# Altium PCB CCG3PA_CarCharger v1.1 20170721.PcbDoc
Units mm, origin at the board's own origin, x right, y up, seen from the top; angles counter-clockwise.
Board outline 152.4 x 101.6 mm, 4 copper layers (Top Layer, MidLayer1, MidLayer2, Bottom Layer); 67 components, 48 nets, 247 pads, 127 vias.
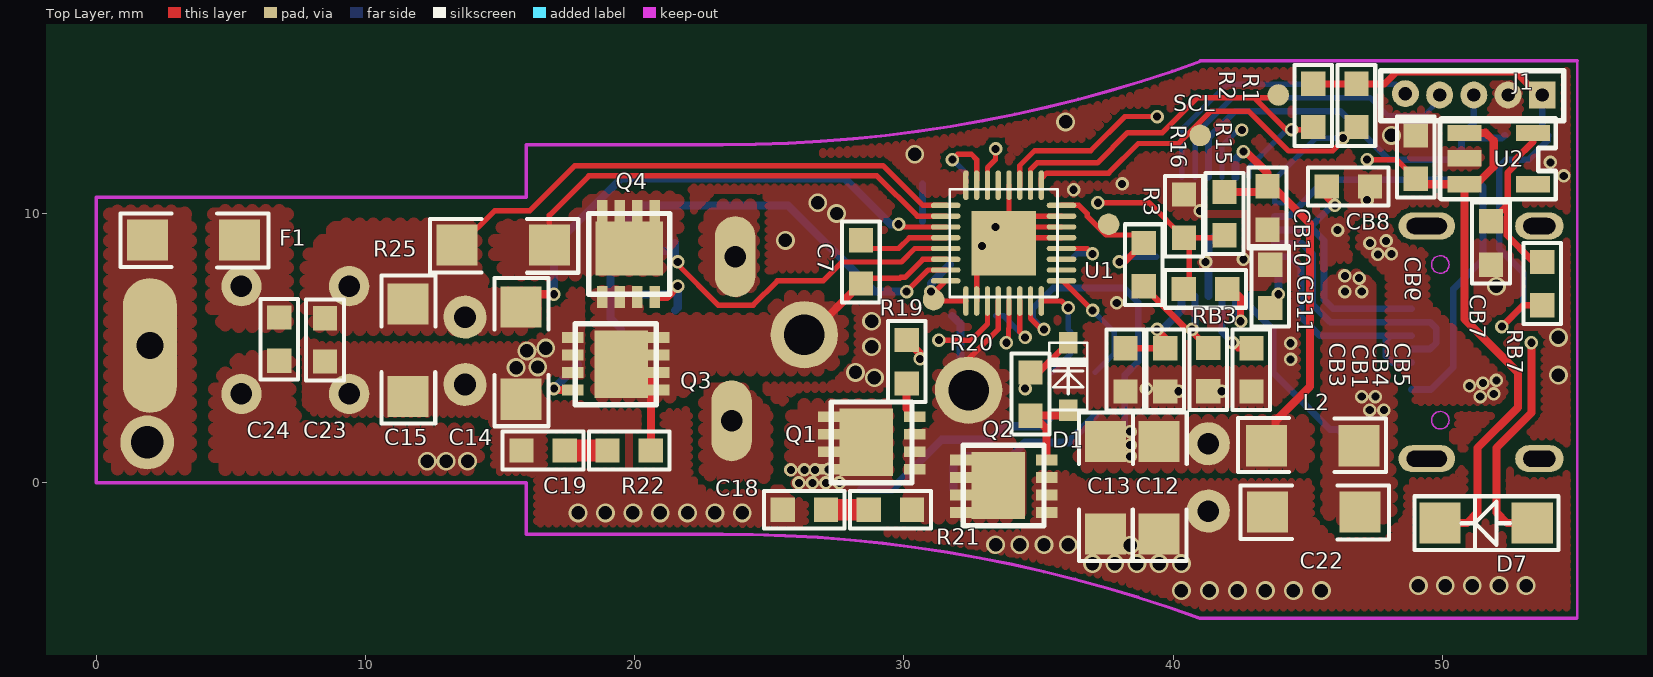
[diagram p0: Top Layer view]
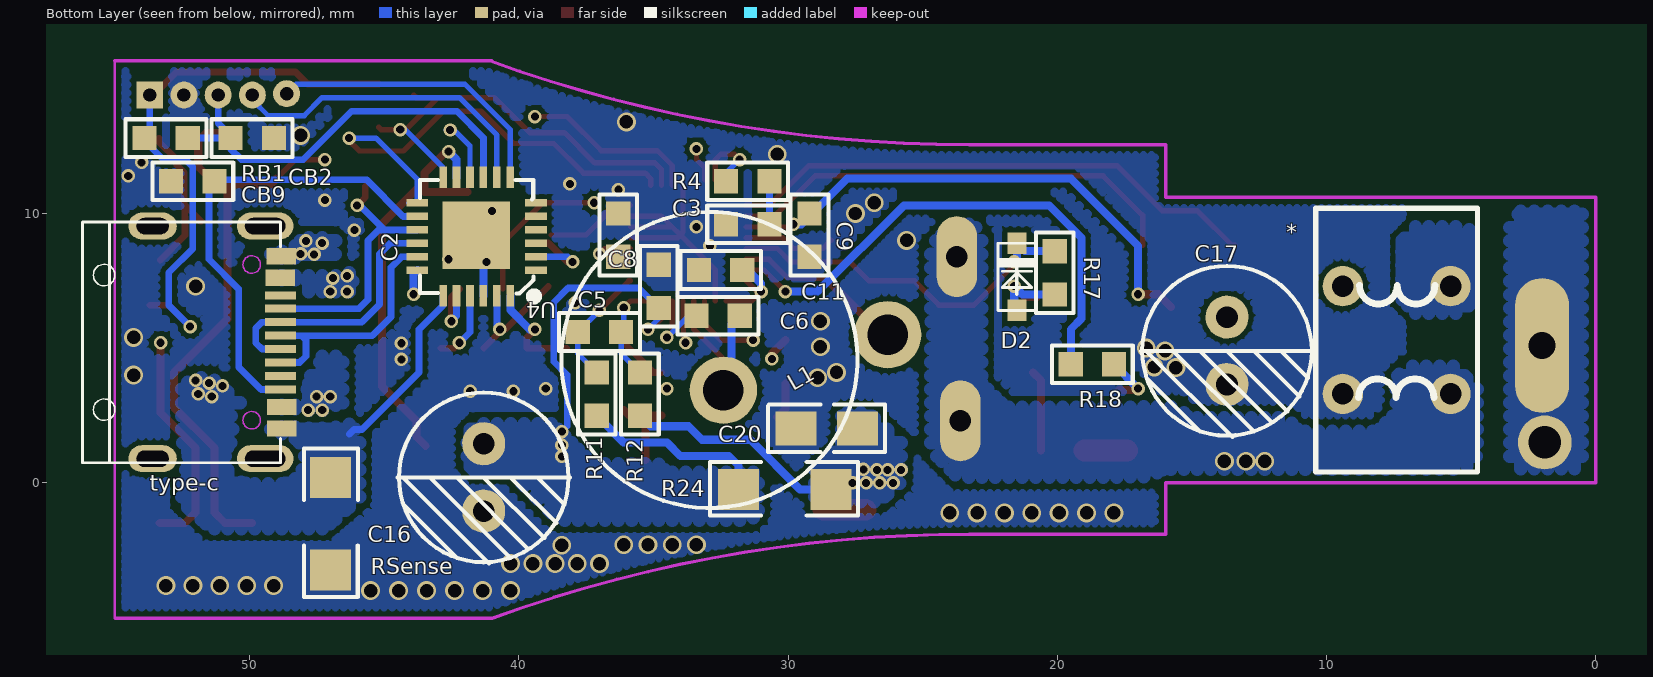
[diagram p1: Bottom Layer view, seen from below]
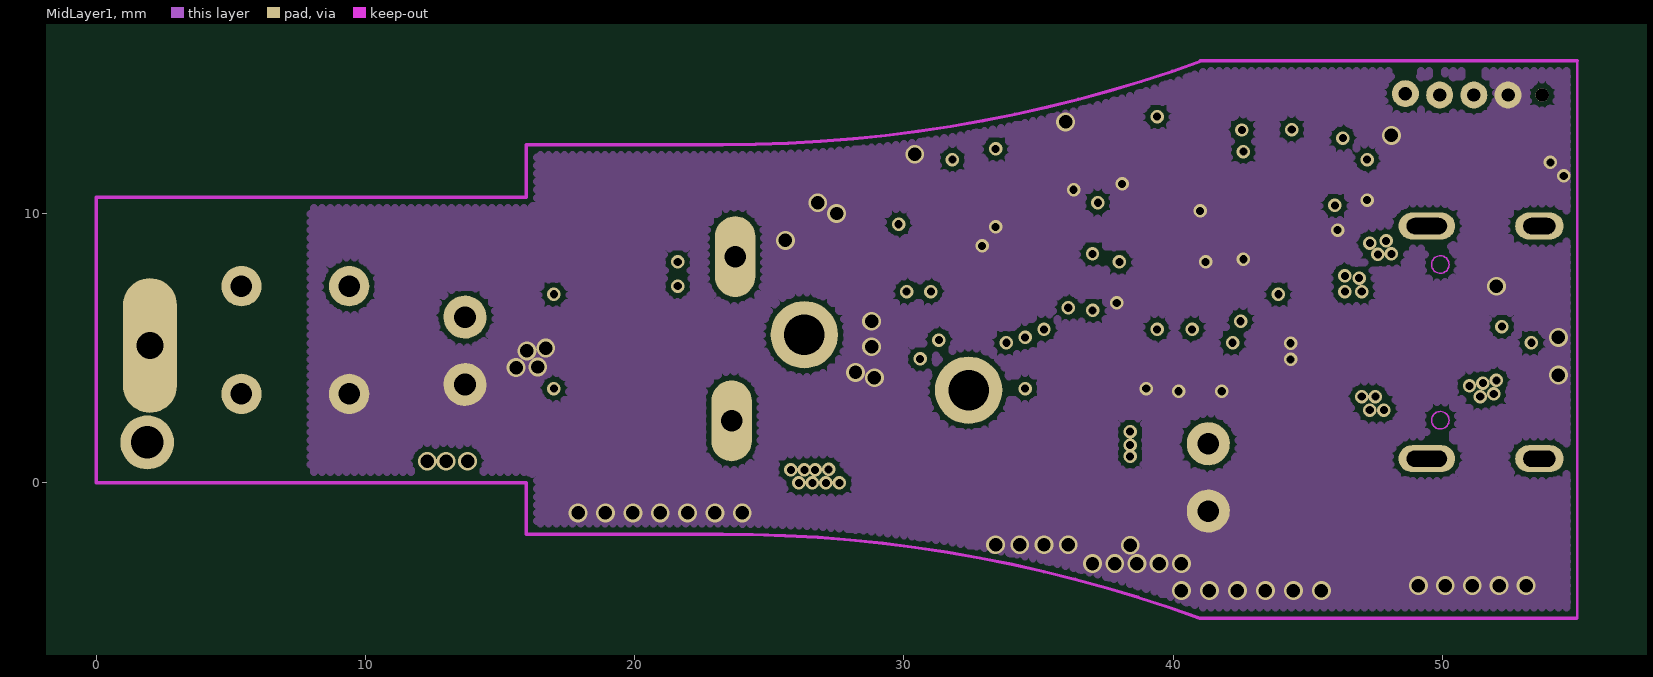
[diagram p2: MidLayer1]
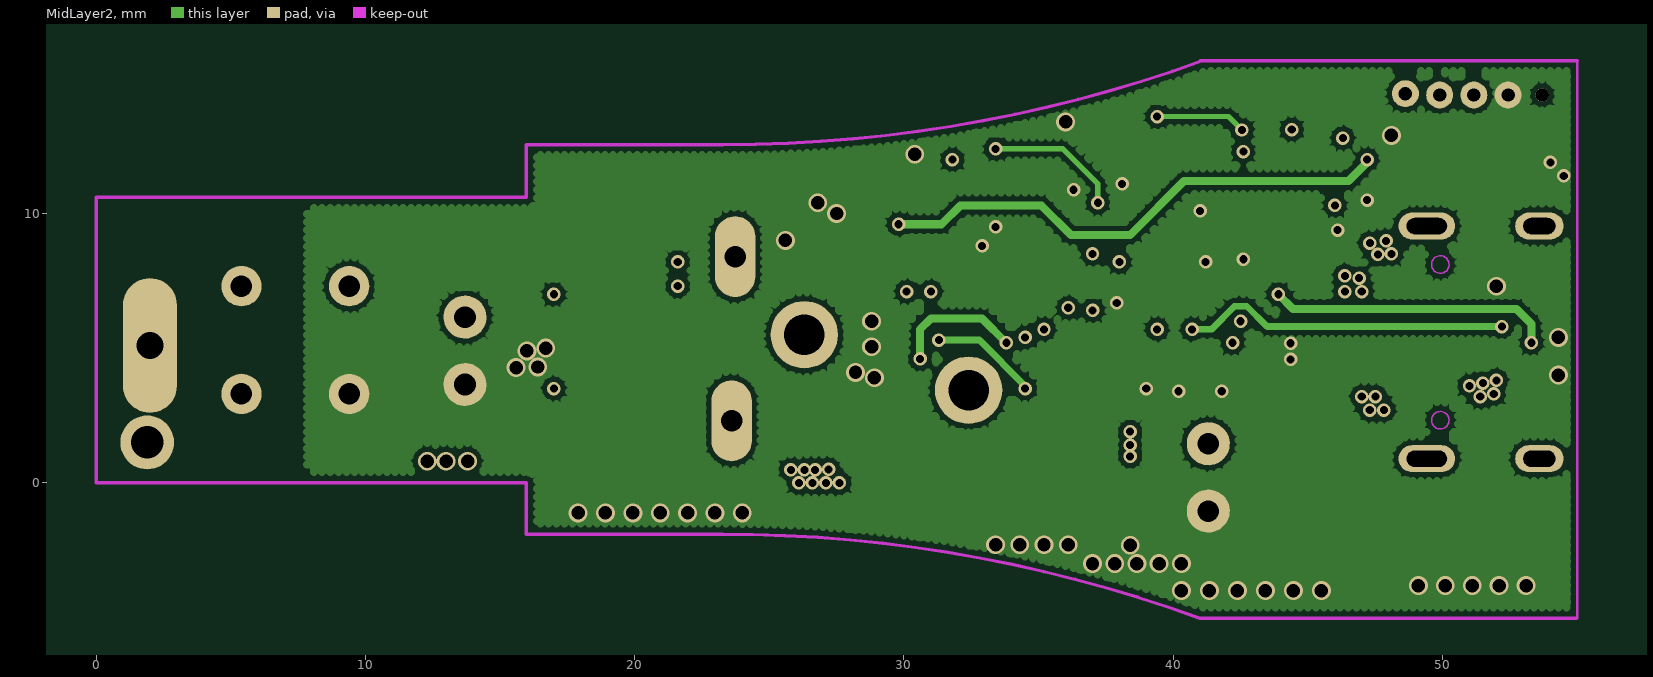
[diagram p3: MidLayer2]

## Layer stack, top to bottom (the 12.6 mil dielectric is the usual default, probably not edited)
Top Layer: signal copper 0.0356
Dielectric: core 0.32, FR-4, Dk 4.8
MidLayer1: signal copper 0.0356
Dielectric: prepreg 0.32, FR-4, Dk 4.8
MidLayer2: signal copper 0.0356
Dielectric: core 0.32, FR-4, Dk 4.8
Bottom Layer: signal copper 0.0356

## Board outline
-65.803,-29.119 86.597,-29.119 86.597,72.481 -65.803,72.481

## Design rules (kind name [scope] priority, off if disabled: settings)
Clearance [All] p1: gap=0.18
ComponentClearance [All] p1: gap=0 collisioncheckmode=3 verticalgap=0 showdistances=FALSE
HoleToHoleClearance [All] p1: gap=0 allowstackedmicrovias=TRUE
MinimumSolderMaskSliver [All] p1: minsoldermaskwidth=0
PlaneConnect [All] p1: planeconnectstyle=Direct reliefexpansion=0.508 reliefentries=4 reliefconductorwidth=0.254 reliefairgap=0.254
PolygonConnect [All] p1: connectstyle=Direct reliefconductorwidth=0.254 reliefentries=4 polygonreliefangle="90 Angle" airgapwidth=0.254
RoutingVias [All] p1: holewidth=0.711 width=1.27 viastyle="Through Hole" minholewidth=0.711 minwidth=1.27 maxholewidth=0.711 maxwidth=1.27
ShortCircuit [InNet('GND') And OnLayer('MidLayer1') vs InNet('SGND') And OnLayer('MidLayer1')] p1: allowed=TRUE
SilkToSilkClearance [All] p1: silktosilkclearance=0
SilkToSolderMaskClearance SilkscreenOverComponentPads [IsPad] p1: minsilkscreentomaskgap=0 clearancetoexposedcopper=TRUE
SolderMaskExpansion [All] p1: expansion=0.102
Width [All] p1: maxlimit=11 minlimit=0.2 preferedwidth=0.3
21 further rules are at their usual default settings.

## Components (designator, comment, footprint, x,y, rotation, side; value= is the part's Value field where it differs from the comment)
* "COMMON" Common1 9.4,3.3 r180 bottom locked
C2 "100nF" 0603 36.3,8.4 r90 bottom
C3 "10nF" 0603 30.7,9.6 r0 bottom
C5 "22nF" 0603 37.8,5.6 r180 bottom
C6 "0.1uF" 0603 31.8,6.2 r0 bottom
C7 "0.1uF" 0603 28.4,9 r270 top
C8 "1uF" 0603 34.8,6.5 r90 bottom
C9 "1uF" 0603 29.2,8.4 r90 bottom
C11 "1uF" 0603 33.3,7.9 r180 bottom
C12 "10uF/35V" 1206#1 40.2,2.3 r270 top
C13 "10uF/35V" 1206#1 38.2,2.3 r270 top
C14 "10uF/35V" 1206#1 16.5,7.3 r270 top
C15 "10uF/35V" 1206#1 12.3,7.4 r270 top
C16 "100uF" C4 41.3,1.4 r270 bottom
C17 "100uF" C4 13.7,6.1 r270 bottom
C18 "1nF" 0603 27.1,-1 r180 top
C19 "1nF" 0603 17.4,1.2 r180 top
C20 "100nF" 0805 26.4,1 r0 bottom
C22 "10uF/25V" 1206#1 47.7,-1.8 r180 top
C23 "0.1uF" 0603 8.5,6.1 r270 top
C24 "0.1uF" 0603 6.803,6.133 r270 top
CB1 "1uF" 0603 39.7,3.4 r90 top
CB2 "0.1u" 0603 49.1,12.8 r0 bottom
CB3 "0.1uF" 0603 38.222,4.992 r270 top
CB4 "1uF" 0603 41.3,5 r270 top
CB5 "0.1uF" 0603 42.9,3.4 r90 top
CB6 "1uF" 0603 49,11.3 r90 top
CB7 "1uF" 0603 51.8,9.7 r270 top
CB8 "390pF" 0603 47.3,11 r180 top
CB9 "390pF" 0603 52.9,11.2 r180 bottom
CB10 "1uF" 0603 43.5,11 r270 top
CB11 "1uF" 0603 43.6,6.5 r90 top
D1 "4148" sod323 36.1,5.2 r270 top
D2 "4148" sod323 21.5,8.9 r270 bottom
D7 "5.1V" D1206 49.9,-1.5 r0 top
F1 "FUSE" 1206#1 6.1,8.3 r180 top
J1 "PIN5" pin5 53.7,14.4 r180 top
L1 "6.8uH" L/DB_MPP 26.3,5.5 r330 bottom locked
L2 "Bead" 1206#1 42.7,2.1 r0 top
Q1 "PK616" PDFN-3*3 30.4,0.5 r180 top
Q2 "PK616" PDFN-3*3 35.3,-1.1 r180 top
Q3 "3482" PDFN-3*3 17.7,5.4 r0 top
Q4 "3482" PDFN-3*3 18.8,6.9 r90 top
R1 "10K" 0603 46.8,14.808 r270 top
R2 "10K" 0603 45.2,14.808 r270 top
R3 "10K" 0603 38.9,8.9 r270 top
R4 "20k" 0603 30.7,11.2 r0 bottom
R11 "2R2" 0603 37.1,2.5 r90 bottom
R12 "2R2" 0603 35.5,2.5 r90 bottom
R15 "100k" 0603 41.9,9.2 r90 top
R16 "24k" 0603 40.4,10.7 r270 top
R17 "20R0" 0603 20.1,7 r90 bottom
R18 "0R0" 0603 17.9,4.4 r0 bottom
R19 "0R0" 0603 30.1,3.7 r90 top
R20 "20R0" 0603 34.7,2.5 r90 top
R21 "2R2" 0603 28.7,-1 r0 top
R22 "2R2" 0603 19,1.2 r0 top
R24 "0R010" 1206#1 32.6,0.481 r180 bottom
R25 "0R005" 1206#1 17.6,8.1 r180 top
RB1 "4.7K" 0603 52.3,12.8 r0 bottom
RB3 "0R0" 0603 40.4,7.2 r0 top
RB7 "10R0/NC" 0603 53.7,6.6 r90 top
RSense "0R005" 1206#2 46.997,-1.519 r270 bottom
type-c "TYPE-C" type-c3 49.1,5.7 r0 bottom locked
U1 "SC8815" TQFN32-4*4L 35.7,7.5 r180 top
U2 "3.3V/NC" SOT-23-5 49.8,13.5 r270 top
U4 "CCG3PA" QFN-24 39.9,7.2 r0 bottom

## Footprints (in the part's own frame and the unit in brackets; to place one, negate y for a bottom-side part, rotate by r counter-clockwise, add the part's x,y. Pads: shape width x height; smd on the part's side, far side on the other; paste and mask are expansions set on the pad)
0603 [mm]
  rect 0.9x0.9 smd: 1(-0.008,0) 2(1.6,0)
  silkscreen extent -0.7,-0.7 2.3,0.7, body extent -0.05,-0.45 1.6,0.45, height 1
0805 [mil]
  rect 60x50 smd: 1(40,-40) 2(130,-40)
  silkscreen extent 0,-75 171,-6, body extent 41,-65 130,-16, height 39
1206#1 [mil]
  rect 60x60 smd: 1(30.24,-28.5) 2(165.24,-28.5)
  silkscreen extent -12,-67 205,12, body extent 30,-59 167,2, height 39
1206#2 [mil]
  rect 60x60 smd: 1(-67.5,0) 2(67.5,0)
  silkscreen extent -110,-38 107,40, body extent -68,-31 70,30, height 39
C4 [mm]
  round 1.6 hole 0.8: 1(-0.05,0) 2(2.45,0)
  silkscreen extent -1.95,-3.2 4.4,3.2, body extent -1.7,-3.1 4.28,2.89, height 8
Common1 [mm]
  round 1.5 hole 0.8: 1(0,0) 2(4,0) 3(0,4) 4(4,4)
  silkscreen extent -1,-2.9 5,6.9
D1206 [mil]
  rect 60x60 smd: 1(135,0) 2(0,0)
  silkscreen extent -37,-39 173,39
L/DB_MPP [mm]
  round 2.5 hole 1.5: 1(0,0) 2(6.312,-1.267)
  silkscreen extent 0.7,-8 11.7,3
PDFN-3*3 [mm]
  rect 0.8x0.4 smd: 1(0,-1.95) 2(3.2,-1.3) 2(3.2,-0.65) 2(3.2,0) 2(3.2,-1.95) 3(0,0) 3(0,-0.65) 3(0,-1.3)
  rect 2x2.5 smd: 2(1.8,-1)
  silkscreen extent 0.1,-2.5 3.1,0.5
pin5 [mm]
  rect 1x1 / inner round 0.5 / far side rect 1x1 hole 0.5: 1(0,0)
  round 1 hole 0.5: 2(1.27,0) 3(2.54,0) 4(3.81,0) 5(5.08,-0.05)
  silkscreen extent -0.8,-0.9 6,0.95
QFN-24 [mm]
  rect 2.5x2.5 smd: 0(1.672,-1.987)
  rect 0.8x0.28 smd: 1(-0.542,-0.691) 2(-0.542,-1.191) 3(-0.542,-1.691) 4(-0.542,-2.191) 5(-0.542,-2.691) 6(-0.542,-3.191) 13(3.862,-3.191) 14(3.862,-2.691) 15(3.862,-2.191) 16(3.862,-1.691) 17(3.862,-1.191) 18(3.862,-0.691)
  rect 0.28x0.8 smd: 7(0.41,-4.143) 8(0.91,-4.143) 9(1.41,-4.143) 10(1.91,-4.143) 11(2.41,-4.143) 12(2.91,-4.143) 19(2.91,0.26) 20(2.41,0.26) 21(1.91,0.26) 22(1.41,0.26) 23(0.91,0.26) 24(0.41,0.26)
  silkscreen extent -0.61,-4.04 3.76,0.43, body extent -0.46,-4.07 3.78,0.17, height 0.72
sod323 [mm]
  rect 0.8x0.7 smd: 1(2.5,0) 2(0,0)
  silkscreen extent 0,-0.7 2.5,0.7
SOT-23-5 [mil]
  rect 23.62x50 smd: 1(20,40) 2(57,40) 3(95,40) 4(95,140) 5(20,140)
  silkscreen extent -1,4 117,173
TQFN32-4*4L [mm]
  round 0.5 on Top Overlay: 0(0.05,0.55)
  rect 2.4x2.4 smd: 0(2,-1.4)
  oval 1.1x0.2 smd: 1(-0.15,0) 2(-0.15,-0.4) 3(-0.15,-0.8) 4(-0.15,-1.2) 5(-0.15,-1.6) 6(-0.15,-2) 7(-0.15,-2.4) 8(-0.15,-2.8) 17(4.15,-2.8) 18(4.15,-2.4) 19(4.15,-2) 20(4.15,-1.6) 21(4.15,-1.2) 22(4.15,-0.8) 23(4.15,-0.4) 24(4.15,0)
  oval 0.2x1.1 smd: 9(0.6,-3.55) 10(1,-3.55) 11(1.4,-3.55) 12(1.8,-3.55) 13(2.2,-3.55) 14(2.6,-3.55) 15(3,-3.55) 16(3.4,-3.55) 25(3.4,0.75) 26(3,0.75) 27(2.6,0.75) 28(2.2,0.75) 29(1.8,0.75) 30(1.4,0.75) 31(1,0.75) 32(0.6,0.75)
  silkscreen extent 0,-3.4 4,0.6
type-c3 [mm]
  rect 1.1x0.6 smd: A1B12(-0.275,-2.715) A4B9(-0.25,-1.915) B1A12(-0.3,3.685) B4A9(-0.3,2.885)
  rect 1.15x0.3 smd: A5(-0.25,-0.765) A6(-0.25,0.235) A7(-0.25,0.735) A8(-0.25,1.735) B5(-0.25,2.235) B6(-0.25,1.235) B7(-0.25,-0.265) B8(-0.25,-1.25)
  oval 2.1x1 hole 0.6 slot 1.5 at 0 deg: GND(0.315,-3.835) GND(0.315,4.805)
  oval 1.8x1 hole 0.6 slot 1.2 at 0 deg: GND(4.495,-3.835) GND(4.495,4.805)
  Keep-Out Layer circle w0.05: c0.815,-2.405 r0.325
  Keep-Out Layer circle w0.05: c0.815,3.375 r0.325
  silkscreen extent -0.26,-3.99 7.09,4.96

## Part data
C2 C3 C5 C6 C7 C8 C9 C11 C12 C13 C14 C15 C18 C19 C20 C22 C23 C24 CB1 CB2 CB3 CB4 CB5 CB6 CB7 CB8 CB9 CB10 CB11: library part CAP, "cap"
C16 C17: library part CAP2
D1 D2: library part "DIODE 1", "DIODE"
D7: library part ZENER, "zener"
L1: library part L, "inductor"
Q1 Q2 Q3 Q4: library part NMOS, "nmos"
R1 R2 R3 R4 R11 R12 R15 R16 R17 R18 R19 R20 R21 R22 R24 R25 RB1 RB3 RB7 RSense: library part RES, "RES"
type-c: library part type-c1
U2: library part GS7138S2, "LDO"

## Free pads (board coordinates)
  oval 2x5 hole 1: 0(2,5.1)
  round 2 hole 1.2: 1(1.9,1.5)
  oval 1.5x3 hole 0.8: 1(23.6,2.3) 1(23.732,8.4)
  round 0.8 smd: 2(37.6,9.6) 2(41,12.9) 2(43.9,14.4) 3(31.1,6.8)

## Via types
v1: diameter 0.5, hole 0.3, Top Layer to Bottom Layer, 79 vias
v2: diameter 0.7, hole 0.5, Top Layer to Bottom Layer, 48 vias

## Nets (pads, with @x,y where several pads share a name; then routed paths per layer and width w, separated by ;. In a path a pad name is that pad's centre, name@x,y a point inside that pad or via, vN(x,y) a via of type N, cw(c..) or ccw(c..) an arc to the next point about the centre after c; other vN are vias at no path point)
3.3V: CB4.1 J1.1 R1.1 R2.1 R3.2 RB1.2 RB7.1 U4.23 | length 38.2
  Top Layer w0.25: R3.2 40.5,5.7 v1(40.7,5.7) 40.7,5.608 CB4.1 ; R2.1@45.2,14.808 47.84,14.808 48.287,15.255 52.713,15.255 53.568,14.4 J1.1 ; v1(52.2,5.8) 52.992,6.592 RB7.1
  MidLayer2 w0.25: v1(40.7,5.7) 41.415,5.7 42.27,6.555 42.73,6.555 43.485,5.8 v1(52.2,5.8)
  Bottom Layer w0.25: v1(40.7,5.7) 40.81,5.81 U4.23 ; v1(52.2,5.8) 53,6.6 53,7.8 52.1,8.7 52.1,11.723 52.377,12 53.2,12 53.9,12.7 RB1.2 ; J1.1 53.7,13.124 RB1.2@53.924,12.9
/CE: pad.2@37.6,9.6 R3.1 U1.8 U4.2 | length 6.1
  Top Layer w0.2: U1.8 36.5,10.3 36.8,10 36.8,9.9 37.5,9.2 R3.1@38.8,9.2
  Top Layer w0.25: v1(38,8.2) 38.192,8.2 R3.1
  Bottom Layer w0.25: v1(38,8.2) 38.191,8.391 U4.2
C-D+: type-c.A6 type-c.B6 U4.17 | length 9.3
  Bottom Layer w0.25: U4.17 44.349,8.391 44.74,8 44.74,6.16 45.435,5.465 48.065,5.465 ; type-c.B6 48.135,4.465 47.9,4.7 47.9,5.3 48.065,5.465 ; type-c.A6 48.065,5.465
C-D-: type-c.A7 type-c.B7 U4.16 | length 10
  Bottom Layer w0.25: U4.16 44.779,8.891 45.17,8.5 45.17,6.622 45.827,5.965 type-c.B7 49.535,5.965 49.768,5.732 49.768,5.2 49.532,4.965 type-c.A7
CC1: CB9.2 type-c.B5 U4.14 | length 17.5
  Bottom Layer w0.25: U4.14 44.291,9.891 45.655,11.255 51.245,11.255 CB9.2 51.5,11 51.5,8.3 50.4,7.2 50.4,4.3 49.565,3.465 type-c.B5
CC2: CB8.2 type-c.A5 U4.15 | length 9.8
  Top Layer w0.25: CB8.2 45.7,10.6 v1(46,10.3)
  Bottom Layer w0.25: U4.15 44.991,9.391 ; v1(46,10.3) 45.9,10.3 44.991,9.391 ; type-c.A5 45.935,6.465 45.6,6.8 45.6,9 45.209,9.391 44.991,9.391
FB: R15.1 R16.2 RB3.1 U1.14 | length 13.5
  Top Layer w0.2: U1.14@33.1,11.25 33.1,11.7 33.4,12 v1(33.4,12.4) ; v1(37.2,10.4) 39.1,10.4 R16.2 R16.2@40.592,9.1 ; RB3.1@40.592,7.2 R16.2@40.592,9.1 ; R15.1 41.808,9.1 R16.2@40.592,9.1
  MidLayer2 w0.2: v1(33.4,12.4) 35.9,12.4 37.2,11.1 v1(37.2,10.4)
GND: *.1 C2.2 C3.2 C8.2 C9.1 C11.1 C12.2 C13.2 C14.2 C15.2 C16.2 C17.2 C18.2 C19.2 C20.2 C22.2 C23.2 CB1.1 CB2.1 CB3.2 CB4.2 CB5.1 CB6.2 CB7.2 CB8.1 CB9.1 CB10.2 CB11.2 J1.2 Q2.3 Q3.3 R16.1 RSense.2 U1.0@33.7,8.9 U1.5 U1.6 U1.7 U1.12 U1.16 U1.26 U2.2 U4.0 U4.22 | length 12.8
  Top Layer w0.2: U1.26 32.7,7.9 33.7,8.9 U1.0@34,9.2 ; U1.12 33.9,9.3 U1.0@34,9.2 ; U1.5 34.1,9.1 U1.0@34,9.2 ; U1.6 U1.0@34.3,9.5 ; U1.7 34.7,9.9 U1.0@34.3,9.5 ; U1.0@34,9.2 U1.0@34.3,9.5
  Bottom Layer w0.3: U4.22 41.31,8.926 U4.0
  other v1: 40.2,3.4 41.8,3.4 38.997,3.5 44.355,4.581 44.355,5.181 37.9,6.681 41.2,8.2 42.6,8.3 32.9,8.8 46.1,9.381 33.4,9.5 41,10.1 47.2,10.5 36.3,10.881 38.1,11.1 54.5,11.4 54,11.9
  other v2: 40.3,-4 41.34,-4 42.38,-4 43.42,-4 44.46,-4 45.5,-4 49.1,-3.819 50.1,-3.819 51.1,-3.819 52.1,-3.819 53.1,-3.819 37,-3 37.825,-3 38.65,-3 39.475,-3 40.3,-3 38.4,-2.319 33.4,-2.3 34.3,-2.3 35.2,-2.3 36.1,-2.3 17.9,-1.119 18.916,-1.119 19.932,-1.119 20.948,-1.119 21.965,-1.119 22.981,-1.119 23.997,-1.119 28.9,3.9 54.3,4 28.2,4.1 15.6,4.281 16.4,4.3 16,4.9 16.7,5 28.797,5.05 54.3,5.4 28.797,6 52,7.3 25.6,9 27.5,10 26.8,10.4 30.4,12.2 48.1,12.9 36,13.4
HD1: R19.2 U1.29 | length 7.3
  Top Layer w0.2: v1(33.8,5.2) 33.88,5.28 33.88,5.73 33.9,5.75 U1.29
  Top Layer w0.3: R19.2 30.6,4.8 v1(30.6,4.6)
  MidLayer2 w0.3: v1(30.6,4.6) 30.6,5.7 31,6.1 32.9,6.1 v1(33.8,5.2)
HD2: D2.2 R17.2 U1.21 | length 13.8
  Top Layer w0.2: v1(21.6,8.2) 21.6,8.1 23.1,6.6 24.4,6.6 25.3,7.5 27,7.5 27.7,8.2 29.9,8.2 30.4,8.7 U1.21
  Bottom Layer w0.3: R17.2 21.2,8.6 D2.2 21.5,8.3 v1(21.6,8.2)
INT: U1.11 U4.10 | length 12.2
  Top Layer w0.2: U1.11 34.3,11.775 34.855,12.33 36.93,12.33 38.2,13.6 v1(39.4,13.6)
  MidLayer2 w0.2: v1(39.4,13.6) 42.05,13.6 v1(42.55,13.1)
  Bottom Layer w0.2: U4.10 41.81,12.51 42.4,13.1 v1(42.55,13.1) v1@42.7,13.1
LD1: D1.2 R20.2 U1.27 | length 8.8
  Top Layer w0.2: v1(31.3,5.3) 32.5,5.3 33.1,5.9 U1.27
  Top Layer w0.25: R20.2 35,4.1 D1.2
  MidLayer2 w0.25: v1(31.3,5.3) 32.8,5.3 34.5,3.6 v1(34.5,3.5)
LD2: R18.2 U1.23 | length 19.5
  Top Layer w0.2: v1(30.1,7.1) 30.9,7.9 U1.23
  Bottom Layer w0.3: R18.2 19.5,5.7 19.1,6.1 19.1,9.1 20.3,10.3 25.7,10.3 28.9,7.1 v1(30.1,7.1)
Net*_2: *.2 C24.2 pad.1@23.6,2.3 pad.1@23.732,8.4
  other v2: 12.297,0.8 13,0.8 13.797,0.8
Net*_4: *.4 C24.1 F1.1
NetC2_1: C2.1 U1.4 | length 2
  Top Layer w0.2: U1.4 36.8,8.7 v1(37,8.5)
  Bottom Layer w0.2: C2.1 36.408,8.5 v1(37,8.5)
NetC3_1: C3.1 R4.1 | length 1.4
  Bottom Layer w0.25: C3.1@30.692,9.7 R4.1@30.692,11.108
NetC5_1: C5.1 R11.2 U1.1 | length 4.5
  Top Layer w0.2: U1.1 35.908,7.5 v1(37.008,6.4)
  Bottom Layer w0.2: v1(37.008,6.4) C5.1 37.808,4.808 R11.2
NetC5_2: C5.2 R12.2 U1.32 | length 3.8
  Top Layer w0.2: U1.32 35.85,6.75 v1(36.1,6.5)
  Bottom Layer w0.2: R12.2 36.2,4.8 C5.2 36.1,5.7 v1(36.1,6.5)
NetC6_2: C6.2 U1.30 | length 2.7
  Top Layer w0.2: U1.30 34.3,5.6 v1@34.4,5.5
  Bottom Layer w0.2: C6.2 33.7,6.2 v1(34.5,5.4)
NetC7_1: C7.1 U1.20 | length 3.4
  Top Layer w0.2: C7.1 28.708,8.7 29.8,8.7 30.2,9.1 U1.20
NetC18_1: C18.1 R21.1 | length 1.6
  Top Layer w0.8: C18.1 R21.1
NetC19_1: C19.1 R22.1 | length 1.6
  Top Layer w0.8: C19.1 R22.1
NetC20_1: C20.1 Q1.2 R12.1 R24.2 | length 8.2
  Bottom Layer w0.3: R24.2 29.557,-0.243 31.4,1.6 33.2,1.6 33.7,2.1 35.108,2.1 R12.1
  other v1: 26.1,0 26.6,0 27.1,0 27.6,0 25.8,0.481 26.3,0.481 26.7,0.481 27.2,0.5
NetC22_1: C22.1 L2.2 type-c.A4B9 type-c.B4A9
  other v1: 47.297,2.7 47.82,2.7 47,3.2 47.508,3.2 46.37,7.1 47,7.1 46.9,7.6 46.37,7.683
NetCB1_2: CB1.2 CB3.1 U4.24 | length 4
  Top Layer w0.25: CB3.1 CB1.2 39.7,5.4 v1(39.4,5.7)
  Bottom Layer w0.3: v1(39.4,5.7) 39.6,5.7 40.31,6.41 U4.24
NetCB5_2: CB5.2 U4.21 | length 2.7
  Top Layer w0.25: v1(42.2,5.2) 42.4,5 CB5.2
  Bottom Layer w0.25: U4.21 41.81,5.59 v1(42.2,5.2)
NetCB7_1: CB7.1 RB7.2 U2.5 | length 6.1
  Top Layer w0.25: CB7.1 52.4,10.308 ; RB7.2@53.308,8.274 52.39,9.192 52.39,9.868 52.4,9.878 52.4,10.308 ; U2.5@53.356,12.792 53.356,12.656 52.7,12 52.7,11.797 52.416,11.513 52.416,10.324 52.4,10.308
NetCB11_1: CB11.1 D7.1 U4.18 | length 19.9
  Top Layer w0.3: v1(53.3,5.2) 53.3,2.6 52,1.3 52,-1.1 52.4,-1.5 D7.1
  MidLayer2 w0.3: v1(43.9,7) 44.445,6.455 52.745,6.455 53.3,5.9 v1(53.3,5.2)
  Bottom Layer w0.3: U4.18 43.853,7.8 43.9,7.8 v1(43.9,7)
NetD1_1: D1.1 Q2.1 R20.1 | length 3.3
  Top Layer w0.3: R20.1 R20.1@34.8,2.492 ; Q2.1 35.3,1.992 R20.1@34.8,2.492 ; D1.1 35.892,2.492 R20.1@34.8,2.492
NetD2_1: D2.1 Q4.1 R17.1 | length 3.6
  Top Layer w0.3: Q4.1 21.2,6.9 v1(21.6,7.3)
  Bottom Layer w0.3: R17.1 21.292,6.992 v1(21.6,7.3) 21.6,6.5 D2.1
NetQ1_1: Q1.1 R19.1 | length 1.4
  Top Layer w0.3: R19.1 30.1,2.75 Q1.1
NetQ3_1: Q3.1 R18.1 | length 2
  Top Layer w0.3: v1(17,3.5) 17.05,3.45 Q3.1
  Bottom Layer w0.3: v1(17,3.5) 17,3.508 R18.1
NetR4_2: R4.2 U1.15 | length 2.9
  Top Layer w0.2: v1(31.8,12) 32,12.2 32.5,12.2 32.7,12 U1.15@32.7,11.25
  Bottom Layer w0.2: v1(31.8,12) 32.3,11.5 R4.2@32.3,11.108
NetRB3_2: RB3.2 U4.20 | length 2.3
  Top Layer w0.25: RB3.2@42.2,7.2 42.5,6.9 v1(42.5,6)
  Bottom Layer w0.25: U4.20 42.31,6.19 v1(42.5,6)
SCL: pad.2@41,12.9 R1.2 U1.9 U4.13 | length 17.7
  Top Layer w0.2: U1.9 35.1,11.3 35.3,11.5 37.6,11.5 38.7,12.6 40.2,12.6 41.4,13.8 42.8,13.8 44.28,12.32 45.92,12.32 v1@46.35,12.75
  Bottom Layer w0.2: U4.13@44.091,10.391 U4.13 43.762,11.262 45.3,12.8 v1(46.3,12.8)
SDA: pad.2@43.9,14.4 R2.2 U1.10 U4.12 | length 16.2
  Top Layer w0.2: U1.10 34.7,11.637 34.943,11.88 37.18,11.88 38.3,13 39.6,13 40.9,14.3 43,14.3 ; pad.2@43.9,14.4 43.8,14.3 43,14.3 ; R2.2 45.108,13.116 v1(44.4,13.116) 44.184,13.116 43,14.3
  Bottom Layer w0.2: U4.12 42.81,11.71 44.216,13.116 v1(44.4,13.116)
SNS2N: *.3 C9.2 C14.1 C15.1 C17.1 C23.1 CB6.1 D7.2 R25.2 U1.17 U1.19 U2.1 U2.3 | length 81.8
  Top Layer w0.2: R25.2 13.524,8.824 14.8,10.1 16.1,10.1 17.78,11.78 29.22,11.78 30.7,10.3 U1.17 ; v1(29.8,9.6) 29.9,9.5 U1.19 ; v1(47.2,12) 48.292,12 CB6.1
  Top Layer w0.3: C14.1 16.244,7 v1(17,7) ; CB6.1 49.205,11.087 U2.3 ; D7.2 50.9,-1.5 51.3,-1.1 51.3,1.3 52.8,2.8 52.8,4.1 50.816,6.084 U2.3 ; U2.1 51.592,12.992 51.6,13 51.9,12.7 51.9,11.735 51.252,11.087 U2.3
  MidLayer2 w0.3: v1(29.8,9.6) 31.4,9.6 32.1,10.3 35.1,10.3 36.2,9.2 38.4,9.2 40.4,11.2 46.5,11.2 47.2,11.9 v1(47.2,12)
  Bottom Layer w0.3: v1@16.9,7 v1@17,7.1 ; v1(17,7) v1@17,7.1 ; v1(29.8,9.6) 29.5,9.6 27.8,11.3 19.5,11.3 17,8.8 v1@17,7.1
SNS2P: Q4.2 R25.1 U1.18 | length 17.1
  Top Layer w0.2: R25.1 16.832,9.932 18.3,11.4 29,11.4 30.5,9.9 U1.18
SW1: C6.1 L1.2 Q1.3 Q2.2 R21.2 U1.28 | length 6.8
  Top Layer w0.2: L1.2 32.4,4.6 33.5,5.7 U1.28
  Bottom Layer w0.3: C6.1 32.1,5.892 32.1,3.741 L1.2
SW2: C7.2 L1.1 Q3.2 Q4.3 R22.2 U1.22 | length 9.4
  Top Layer w0.2: C7.2 28.6,7.6 29.85,7.6 29.88,7.63 30.03,7.63 30.7,8.3 U1.22
  Top Layer w0.3: R22.2 20.6,3.8 Q3.2@20.9,4.1 ; L1.1 26.5,5.5 C7.2
SWD_CLK: J1.4 U4.8 | length 11.9
  Bottom Layer w0.2: U4.8 40.81,12.91 42.2,14.3 47.3,14.3 47.97,13.63 49.3,13.63 49.89,14.22 J1.4
SWD_IO: J1.5 U4.7 | length 10.9
  Bottom Layer w0.2: U4.7 40.31,13.11 42,14.8 48.27,14.8 J1.5
VCC: C11.2 pad.3 U1.24 U1.25 | length 3.5
  Top Layer w0.2: U1.24 31.15,7.1 v1(31,7.1) 31.35,6.75 U1.25
  Bottom Layer w0.3: v1(31,7.1) 31,7.4 C11.2@31.7,8.1
VIN+: F1.2 pad.0 pad.1@1.9,1.5
VOUT: C8.1 C12.1 C13.1 C16.1 CB10.1 L2.1 R11.1 R15.2 R24.1 U1.31 U4.11 | length 34.1
  Top Layer w0.2: U1.31 34.7,6.1 v1@35.1,5.7
  Top Layer w0.3: R15.2 CB10.1@43.5,10.8 ; v1@42.6,12.4 43.5,11.5 CB10.1 43.692,11.008 45.08,9.62 45.08,3.58 43.8,2.3 43.8,1.708 L2.1
  Bottom Layer w0.2: C8.1 34.8,6.1 v1(35.2,5.7)
  Bottom Layer w0.25: C8.1 35.544,7.236 38.164,7.236 38.7,6.7 38.7,4.5 38.2,4 38.2,2.1 v1(38.4,1.9)
  Bottom Layer w0.3: R24.1 31.832,0.632 32.2,1 34,1 34.5,1.5 36.108,1.5 R11.1 ; U4.11 42.31,12.01 v1(42.6,12.3)
  other v1: 38.4,0.981 38.4,1.4
VSS_C: RSense.1 type-c.A1B12 type-c.B1A12 U4.19 | length 6.8
  Bottom Layer w0.25: U4.19 42.81,6.59 43.7,5.7 43.7,4.1 45.819,1.981 46.116,1.981 46.297,1.8
  other v1: 51.4,3.2 51.9,3.3 51,3.6 51.5,3.7 52,3.8 47.6,8.481 48.1,8.5 47.3,8.9 47.9,8.981
XRES: CB2.2 J1.3 RB1.1 U4.9 | length 16
  Bottom Layer w0.25: U4.9 41.31,12.81 42.3,13.8 46.2,13.8 48,12 50.3,12 50.7,12.4 CB2.2 52.2,12.8 52.3,12.9 RB1.1@52.316,12.9 ; CB2.2@50.65,12.85 51.16,13.36 J1.3
pads on no net: type-c.A8 type-c.B8 type-c.GND U1.0@35.65,6.95 U1.2 U1.3 U1.13 U2.4 U4.1 U4.3 U4.4 U4.5 U4.6

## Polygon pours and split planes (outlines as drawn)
SW1 on Top Layer "Bottom Layer-No Net" (hatched 90Degree grid 0.5 track 0.5, remove dead copper, pour order 54): 33.3,4.5 33.1,4.7 32.1,4.7 31.9,4.7 31.6,4.4 31.3,4.1 31.3,3.8 31.3,2.1 31.1,1.9 31,1.8 30.4,1.8 30.3,1.8 30.2,1.7 30.2,0.3 30.2,-0.9 30.5,-1.2 30.6,-1.3 32.2,-1.3 34.1,-1.3 34.3,-1.1 34.3,-0.3 34.3,1.1 34,1.4 33.7,1.7 33.7,2.7 33.7,4.1 33.3,4.5
VOUT on Top Layer "Bottom Layer-No Net" (hatched 90Degree grid 0.5 track 0.5, remove dead copper, pour order 52): 44.971,2.3 42.682,2.3 37.072,2.3 36.958,2.2 36.5,1.8 36.5,1.7 36.5,0.8 36.729,0.6 42.109,0.6 44.971,0.6 45.086,0.7 45.2,0.8 45.2,2.1
NetC20_1 on Top Layer "Bottom Layer-No Net" (hatched 90Degree grid 0.5 track 0.5, remove dead copper, pour order 50): 29.3,2.9 27.5,2.9 26.2,2.9 26,2.669 25.8,2.438 25.8,1.862 25.8,0.246 26.1,-0.1 27,-0.1 29.4,-0.1 29.4,2.785
SW2 on Top Layer "Bottom Layer-No Net" (hatched 90Degree grid 0.5 track 0.5, remove dead copper, pour order 49): 20.1,6.9 19.9,7.1 19.8,7.1 18.7,7.1 18.6,7 18.6,6.5 18.6,3.4 18.7,3.3 18.8,3.2 20.5,3.2 21.6,3.2 21.9,3.5 22.6,4.2 23.4,4.2 27.1,4.2 27.4,4.5 27.7,4.8 27.7,5.4 27.7,6.1 27.1,6.7 26.9,6.9 26.2,6.9 25.6,6.9 25.3,6.6 24.8,6.1 24.1,6.1 20.4,6.1 20.1,6.4
SNS2P on Top Layer "Bottom Layer-No Net" (hatched 90Degree grid 0.5 track 0.5, remove dead copper, pour order 48): 21.6,10.6 18.5,10.6 18,10.1 17.5,9.6 16.6,9.6 15.2,9.6 14.9,9.3 14.8,9.2 14.8,8.9 14.8,8.3 15.1,8 15.376,7.724 18.121,7.724 18.297,7.9 20.1,7.9 20.876,7.9 20.956,7.981 20.981,8.005 20.981,8.481 20.981,8.581 21.6,9.2
SNS2N on Top Layer "Bottom Layer-No Net" (hatched 90Degree grid 0.5 track 0.5, remove dead copper, pour order 47): 16.3,7.034 15.5,7.034 14.8,7.034 14.3,7.547 14.1,7.753 14.1,8.574 14.1,9.292 13.8,9.6 12.3,9.6 9,9.6 8.8,9.395 7.8,8.368 7.8,8.061 7.8,6.316 8.1,6.008 8.4,5.7 9.6,5.7 15.9,5.7 16.3,6.111
NetC22_1 on Top Layer "Bottom Layer-No Net" (hatched 90Degree grid 0.5 track 0.5, remove dead copper, pour order 46): 48.1,2.5 48.1,3.5 48.1,3.719 47.7,4.119 47.3,4.519 47.3,5.819 47.3,7.319 47,7.619 46.917,7.703 46.47,7.703 46.164,7.703 45.897,7.436 45.7,7.239 45.7,6.5 45.7,-1.081 46,-1.381 46.6,-1.381 47.719,-1.381 48.1,-1
VIN+ on Top Layer "BottomLayer-VOUT-2" (hatched 90Degree grid 0.5 track 0.5, remove dead copper, pour order 33): 2.6,10.3 2.5,10.4 0.1,10.4 -0.3,10 -0.5,9.8 -0.5,9.1 -0.5,0 0.1,-0.6 0.2,-0.7 2,-0.7 2.5,-0.7 3,-0.2 3.5,0.3 3.5,5.9 3.5,9.8 2.9,10.4
Net*_4 on Top Layer "Bottom Layer-No Net" (hatched 90Degree grid 0.5 track 0.5, remove dead copper, pour order 28): 7.1,5.813 4.862,5.813 4.303,6.313 4.303,6.413 4.303,9.914 4.527,10.114 4.639,10.214 5.981,10.214 6.876,10.214 7.1,10.014
Net*_2 on Top Layer "Bottom Layer-No Net" (hatched 90Degree grid 0.5 track 0.5, remove dead copper, pour order 34): 12.9,-0.016 5.196,-0.016 4.8,0.381 4.4,0.781 4.4,1.481 4.4,3.681 4.8,4.081 5.4,4.681 6.3,4.681 7,4.681 7.1,4.581 7.2,4.481 7.2,3.881 7.2,2.681 7.8,2.081 7.9,1.981 14.2,1.981 14.2,0.381 13.7,-0.119
Net*_2 on Top Layer "Bottom Layer-No Net" (hatched 90Degree grid 0.5 track 0.5, remove dead copper, pour order 37): 24.9,2.6 24,3.5 23.4,3.5 22.9,3.5 22.8,3.4 22.6,3.2 22.6,2.9 22.6,0.5 22.8,0.3 22.9,0.2 23.3,0.2 24.8,0.2 24.9,0.3 24.9,2.5
Net*_2 on Top Layer "Bottom Layer-No Net" (hatched 90Degree grid 0.5 track 0.5, remove dead copper, pour order 38): 24.4,10.3 23.2,10.3 22.6,9.7 22.6,8.5 22.6,7.9 23.1,7.4 23.4,7.1 23.9,7.1 24.1,7.1 24.4,7.4
GND on Top Layer "Bottom Layer-No Net" (hatched 90Degree grid 0.3 track 0.3, remove dead copper, pour order 43): 55.992,18.985 54.192,17.185 9.992,17.185 7.672,14.865 7.672,0.504 15.292,-7.115 56.192,-7.115 56.192,18.585
VSS_C on Top Layer "Bottom Layer-No Net" (hatched 90Degree grid 0.3 track 0.3, remove dead copper, pour order 32): 49,3 51.5,3 52,3 52.2,3.2 52.297,3.297 52.297,3.803 52.297,3.82 51.797,4.32 49.4,6.717 49.4,7.6 49.4,8.4 48.5,9.3 48.3,9.5 47.4,9.5 47.1,9.5 47,9.4 46.9,9.3 46.9,8.9 46.9,8.767 47.464,8.203 48,7.667 48,6.8 48,4.7 48.8,3.9 49,3.7 49,3.2
VOUT on Bottom Layer "Bottom Layer-No Net" (hatched 90Degree grid 0.5 track 0.5, remove dead copper, pour order 53): 31.103,0.4 34.5,0.4 34.8,0.7 36.603,0.7 37.253,0.7 37.453,0.9 38.753,2.2 39.8,2.2 41.584,2.2 41.903,1.881 41.903,1.381 41.903,0.703 41.8,0.6 41.6,0.4 41.003,0.4 40.303,0.4 39.8,-0.103 38.503,-1.4 33.8,-1.4 31.4,-1.4 31.119,-1.119 31.119,-1.116 31.103,-1.1
NetC20_1 on Bottom Layer "Bottom Layer-No Net" (hatched 90Degree grid 0.5 track 0.5, remove dead copper, pour order 51): 28,2.6 27,2.6 25.8,1.5 25.8,0.657 25.8,0.033 26.3,-0.425 26.6,-0.7 28.3,-0.7 28.9,-0.7 29,-0.608 29,0.217 29,0.492 28.6,0.858 28,1.408 28,2.508
VSS_C on Bottom Layer "Bottom Layer-No Net" (hatched 90Degree grid 0.5 track 0.5, remove dead copper, pour order 45): 49.106,2.263 46.406,2.263 46.106,2.005 45.906,1.832 45.906,1.315 45.906,-0.58 46.206,-0.838 47.206,-1.7 49.606,-1.7 51.406,-1.7 51.706,-1.442 52.506,-0.752 52.506,1.66 52.506,3.555 52.106,3.9 51.406,3.9 49.706,2.435 49.321,2.104 48.806,2.104
VSS_C on Bottom Layer "Bottom Layer-No Net" (hatched 90Degree grid 0.5 track 0.5, remove dead copper, pour order 44): 49.2,8.7 48.8,9.1 47.6,9.1 46.9,9.1 46.8,9 46.8,8.5 46.9,8.4 47,8.3 49.2,8.3
VIN+ on Bottom Layer "BottomLayer-VOUT-2" (hatched 90Degree grid 0.5 track 0.5, remove dead copper, pour order 35): 2.9,9.963 2.8,10.1 0.8,10.1 0.5,10.1 0.2,9.689 0.2,9.278 0.2,0.648 0.6,0.1 1.7,0.1 2.6,0.1 2.8,0.374 3.2,0.922 3.2,1.47 3.2,9.552 2.9,9.963
Net*_2 on Bottom Layer "Bottom Layer-No Net" (hatched 90Degree grid 0.5 track 0.5, remove dead copper, pour order 29): 22.803,9.1 22.803,5.1 22.803,4.3 22.803,3.7 22.403,3.3 21.903,2.8 18.003,2.8 17.003,2.8 15.903,1.7 15.703,1.5 15.703,0.6 17.203,0.6 17.603,0.2 23.303,0.2 23.703,0.2 24.303,0.8 24.703,1.2 24.703,2.2 24.703,8.8 24.203,9.3 23.903,9.6 23.603,9.6 23.103,9.6
Net*_2 on Bottom Layer "Bottom Layer-No Net" (hatched 90Degree grid 0.5 track 0.5, remove dead copper, pour order 31): 18.909,0.219 12.712,0.219 5.212,0.219 5.012,0.419 4.412,1.02 4.412,1.519 4.412,3.519 4.712,3.819 5.212,4.319 5.812,4.319 7.012,4.319 7.112,4.219 7.412,3.919 7.412,3.219 7.412,2.619 7.712,2.319 8.112,1.919 10.112,1.919 11.012,1.919 11.412,2.319 11.512,2.419 12.612,2.419 15.112,2.419 15.512,2.819 17.112,2.819
NetC22_1 on Bottom Layer "Bottom Layer-No Net" (hatched 90Degree grid 0.5 track 0.5, remove dead copper, pour order 39): 48.728,7.701 48.614,7.8 46.1,7.8 46.1,7.217 46.235,7.1 46.37,7.1 48.93,7.1 49.065,7.217 49.2,7.333 49.2,7.8 46.504,7.8 46.37,7.683
NetC22_1 on Bottom Layer "Bottom Layer-No Net" (hatched 90Degree grid 0.5 track 0.5, remove dead copper, pour order 40): 49.2,3.5 48.412,3.5 47.85,3.5 47.738,3.9 47.512,4.7 47.175,4.7 46.5,4.7 46.5,2.7 49.2,2.7
Net*_4 on Bottom Layer "Bottom Layer-No Net" (hatched 90Degree grid 0.5 track 0.5, remove dead copper, pour order 41): 6.903,9.3 6.703,9.5 5.003,9.5 4.803,9.5 4.703,9.4 4.603,9.3 4.603,8.8 4.603,6.7 4.803,6.5 5.003,6.3 5.303,6.3 6.703,6.3 6.903,6.5 7.203,6.8 7.203,7.7 7.203,9 6.903,9.3
GND on Bottom Layer "Bottom Layer-No Net" (hatched 90Degree grid 0.3 track 0.3, remove dead copper, pour order 42): 55.167,19.455 54.367,18.655 9.167,18.655 9.167,18.155 7.567,16.555 7.167,16.155 7.167,8.655 7.167,-2.645 7.967,-3.445 10.367,-5.845 55.667,-5.845 55.667,19.455 56.067,19.855
GND on MidLayer1 "BottomLayer-VOUT-2" (hatched 90Degree grid 0.3 track 0.3, remove dead copper, pour order 36): 54.381,18.003 53.494,16.991 13.28,16.991 11.111,16.991 9.14,14.744 7.957,13.396 7.957,9.8 7.957,-2.897 10.421,-5.706 11.505,-6.942 56.056,-6.942 56.056,16.43 54.677,18.003
GND on MidLayer2 "Bottom Layer-No Net" (hatched 90Degree grid 0.3 track 0.3, remove dead copper, pour order 30): 57.43,18.198 14.786,18.198 9.688,12.698 7.834,10.698 7.834,4.698 7.834,-2.102 9.595,-4.002 13.21,-7.902 56.317,-7.902 58.078,-7.902 60.396,-5.402 59.376,-4.302 59.376,17.998

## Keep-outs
Keep-Out Layer:
  lines w0.1: 55,-5 55,15.678
  lines w0.127: 23.167,-1.908 cw(c23.279,-53.689) 40.989,-5.031 54.989,-5.031 ; 23.279,-1.912 15.982,-1.912 15.982,0 0,0 0,10.596 15.982,10.596 ; 41,15.678 55,15.678 ; 41.1,15.678 cw(c23.39,64.337) 23.279,12.555 15.982,12.555 ; 15.982,10.596 15.982,12.555 ; 15.982,10.596 15.982,12.555

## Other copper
Top Layer:
  pour cut-out: 31.55,10.3 32.3,11.05 35.1,11.05 35.85,10.3 36.6,10 37.026,9.066 35.7,7.3 35.15,6.75 32.3,6.75 31.55,7.5
Bottom Layer:
  pour cut-out: 43.762,9.391 43.7,9.453 43.7,11.1 39.921,11.1 39.84,11.181 39.6,10.941 39.6,7.277 39.977,6.9 43.2,6.9 43.762,7.462

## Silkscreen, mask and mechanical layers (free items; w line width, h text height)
Top Overlay:
  text "SCL" at 40,13.8 h0.6
Top Solder:
  rectangle: 25.3,8.7 26.6,10.8
  rectangle: 16.7,-1.6 24.4,-0.6
  rectangle: 22.803,7.1 24.6,10.4
  rectangle: 22.6,0.4 24.5,3.8
  rectangle: 44.6,0.4 45.9,2.5
  rectangle: 6.5,7 8.5,8
  rectangle: 6.5,2.4 8.5,3.6
Bottom Solder:
  rectangle: 34.5,12.7 38.9,13.3
  rectangle: 16.3,0.2 22.5,1.3
  rectangle: 16.2,1.5 22.6,2.6
  rectangle: 22.9,7.1 24.5,9.6
  rectangle: 22.7,0.5 24.297,3.6
  rectangle: 48.2,-4.2 51.7,-0.8
Mechanical 1:
  lines w0.127: 1.882,4.398 ccw(c2.232,4.398) 2.582,4.398 2.582,6.198 ccw(c2.232,6.198) 1.882,6.198 1.882,4.398 ; 23.332,1.104 23.332,3.504 23.932,3.504 23.932,1.104 23.332,1.104 ; 23.332,7.134 23.332,9.534 23.932,9.534 23.932,7.134 23.332,7.134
